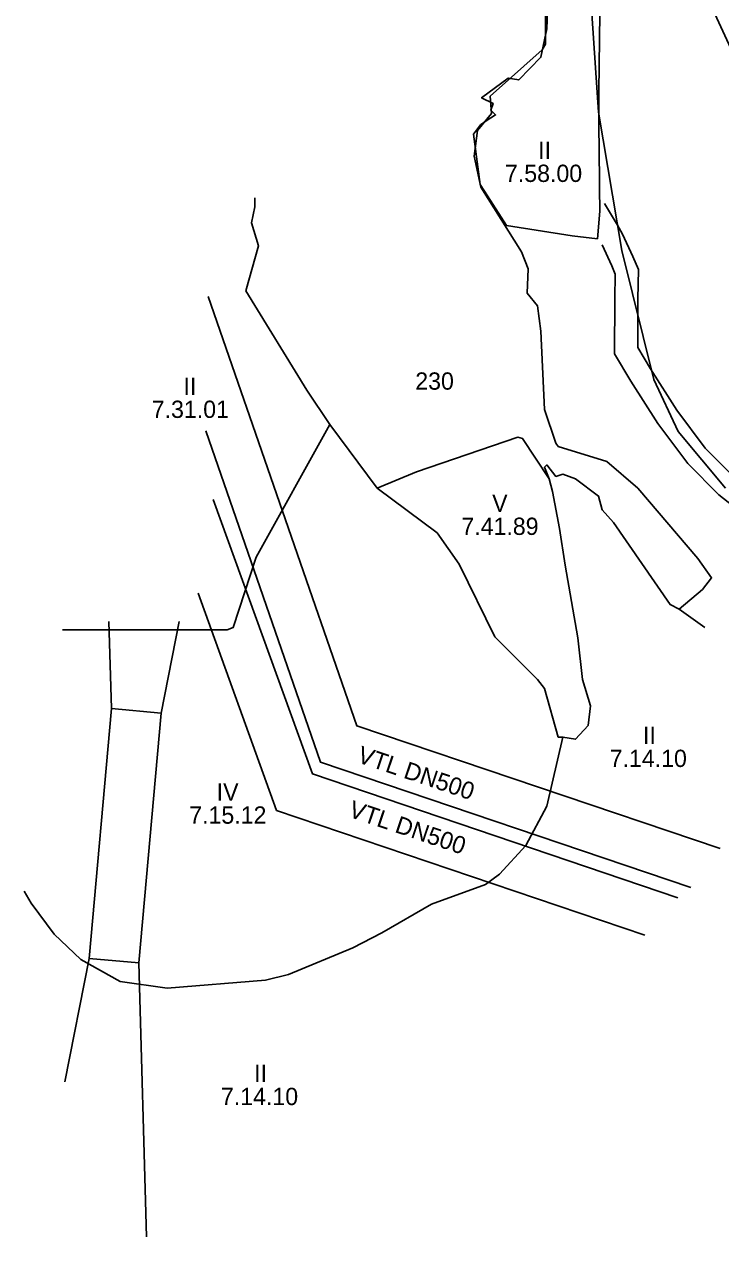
# Model space of a CAD drawing. Extents: x -694504 to -690518, y -983661 to -978958.
# Drawn here: x -693422 to -692818, y -983661 to -982609 of the extents above; entities that cross this region are included whole.
import ezdxf

# ---------------------------------------------------------------- set-up
doc = ezdxf.new("R2010")
doc.units = 0
for name, color, linetype in [('bezpečnostní pásmo', 7, 'Continuous'), ('BPEJ', 7, 'Continuous'), ('lokální biocentra', 7, 'Continuous'), ('lokální biokoridory', 7, 'Continuous'), ('plocha pro SLZ', 7, 'Continuous'), ('třídy přednosti v ochraně ZP', 7, 'Continuous'), ('VTL plynovod', 7, 'Continuous')]:
    doc.layers.add(name, color=color, linetype=linetype)

msp = doc.modelspace()

# ---------------------------------------------------------------- linework, layer by layer
at = {"layer": 'bezpečnostní pásmo'}
for points in [[(-692819.1, -983324.6), (-693134.2, -983218), (-693262.9, -982845.7)], [(-693271.8, -983102.9), (-693203.6, -983291.5), (-692884.2, -983399.8)]]:
    msp.add_lwpolyline(points, dxfattribs=at)
at = {"layer": 'BPEJ'}
for p, q in [((-693222.4, -982767.8), (-693222.4, -982760.1)), ((-692854.4, -983116.8), (-692832.2, -983132.9)), ((-693416.4, -983371.8), (-693422.5, -983361.5))]:
    msp.add_line(p, q, dxfattribs=at)
for points in [[(-692814.4, -983011.8), (-692855.4, -982962.8), (-692876.4, -982917.8), (-692904.4, -982805.8), (-692924.4, -982685.8), (-692931.4, -982582.8), (-692926.4, -982434.8), (-692926.4, -982406.8), (-692928.4, -982259.8), (-692918.4, -982237.8), (-692888.4, -982198.8), (-692863.4, -982207.8), (-692863.4, -982207.8), (-692864.4, -982295.8), (-692861.4, -982330.8), (-692862.4, -982461.8), (-692825.4, -982596.8), (-692794.4, -982663.8)], [(-692794.4, -982663.8), (-692825.4, -982596.8), (-692862.4, -982461.8), (-692861.4, -982330.8), (-692864.4, -982295.8), (-692863.4, -982207.8), (-692844.4, -982207.8), (-692817.4, -982201.8)], [(-692854.4, -983116.8), (-692834.4, -983099.8), (-692826.4, -983089.8), (-692838.4, -983072.8), (-692890.4, -983011.8), (-692917.4, -982988.8), (-692959.4, -982975.8), (-692961.4, -982972.8), (-692971.4, -982943.8), (-692974.4, -982875.8), (-692977.4, -982853.8), (-692986.4, -982842.8), (-692985.4, -982821.8), (-692991.4, -982806.8), (-693026.4, -982750.8), (-693032.4, -982723.8), (-693029.4, -982701.8), (-693017.4, -982686.8), (-693018.4, -982671.8), (-692973.4, -982631.8), (-692970.4, -982626.8), (-692970.4, -982559.8)], [(-693157.4, -982956.8), (-693177.4, -982926.8), (-693230.4, -982840.8), (-693219.4, -982801.8), (-693225.4, -982781.8), (-693222.4, -982767.8)], [(-693116.4, -983011.8), (-693157.4, -982956.8), (-693221.4, -983071.8), (-693241.4, -983132.8), (-693246.4, -983134.8), (-693389.4, -983134.8)], [(-692967.4, -983003.8), (-692971.4, -982993.8), (-692969.4, -982991.8), (-692961.4, -983001.8), (-692955.4, -982999.8), (-692944.4, -983003.8), (-692924.4, -983018.8), (-692921.4, -983030.8), (-692911.4, -983041.8), (-692862.4, -983112.8), (-692854.4, -983116.8)], [(-692955.4, -983227.8), (-692969.4, -983287.8), (-692987.4, -983321.8), (-693010.4, -983346.8), (-693022.4, -983355.8), (-693069.4, -983372.8), (-693112.4, -983397.8), (-693137.4, -983410.8), (-693193.4, -983433.8), (-693213.4, -983438.8), (-693298.4, -983445.8), (-693339.4, -983439.8), (-693373.4, -983420.8), (-693396.4, -983398.8), (-693416.4, -983371.8)]]:
    msp.add_lwpolyline(points, dxfattribs=at)
msp.add_lwpolyline([(-692967.4, -983003.8), (-692964.4, -983014.8), (-692958.4, -983046.8), (-692953.4, -983078.8), (-692942.4, -983141.8), (-692938.4, -983177.8), (-692931.4, -983200.8), (-692933.4, -983217.8), (-692944.4, -983229.8), (-692955.4, -983227.8), (-692959.4, -983227.8), (-692971.4, -983185.8), (-692977.4, -983177.8), (-693014.4, -983140.8), (-693045.4, -983077.8), (-693064.4, -983050.8), (-693116.4, -983011.8), (-693082.4, -982997.8), (-692994.4, -982967.8), (-692990.4, -982968.8), (-692967.4, -983003.8)], close=True, dxfattribs=at)
at = {"layer": 'lokální biocentra'}
msp.add_lwpolyline([(-692967.4, -982557.2), (-692969.2, -982613.5), (-692974.4, -982638.1), (-692993.6, -982657.8), (-693002.7, -982656.2), (-693025.9, -982673.3), (-693015.9, -982678.2), (-693017.9, -982684), (-693013.8, -982688.2), (-693022, -982693.4), (-693026.9, -982696.8), (-693032.8, -982704.8), (-693028.5, -982737.6), (-693027, -982748.5), (-693020.8, -982758.3), (-693004.4, -982784.1), (-692947.4, -982793.1), (-692925.4, -982795.5), (-692923.4, -982771.6), (-692923.7, -982751.7), (-692923.7, -982745.1), (-692924.2, -982695.9), (-692924.1, -982667.8), (-692923.2, -982599.9)], dxfattribs=at)
at = {"layer": 'lokální biokoridory'}
for points in [[(-692656.6, -983087.7), (-692694.3, -983066.4), (-692712.1, -983059), (-692716.8, -983055.4), (-692782.5, -983022), (-692806.6, -983002.7), (-692831.9, -982977.3), (-692856.5, -982944.3), (-692879.5, -982908.5), (-692890.5, -982890), (-692890.3, -982847.9), (-692889.9, -982822.3), (-692894.6, -982811), (-692903.6, -982791.5), (-692908, -982783.9), (-692919.3, -982764.9)], [(-692921.4, -982800.7), (-692912.9, -982819.1), (-692909.9, -982826.2), (-692910.3, -982847.7), (-692910.6, -982895.5), (-692896.5, -982919), (-692872.9, -982955.7), (-692847, -982990.4), (-692820, -983017.6), (-692793.3, -983038.9), (-692727.5, -983072.4), (-692722.2, -983076.5), (-692703.1, -983084.4), (-692665.5, -983105.6)]]:
    msp.add_lwpolyline(points, dxfattribs=at)
at = {"layer": 'plocha pro SLZ'}
for p, q in [((-693346.9, -983203.2), (-693349.1, -983127.6)), ((-693303.8, -983207), (-693288.2, -983127.6)), ((-693387.2, -983527), (-693366.1, -983420)), ((-693316.4, -983661.3), (-693323, -983423.8))]:
    msp.add_line(p, q, dxfattribs=at)
msp.add_lwpolyline([(-693346.9, -983203.2), (-693366.1, -983420), (-693323, -983423.8), (-693303.8, -983207)], close=True, dxfattribs=at)
at = {"layer": 'VTL plynovod'}
for points in [[(-693265, -982962.1), (-693165.6, -983249.6), (-692844.4, -983358.2)], [(-693258.6, -983021.9), (-693172.5, -983259.8), (-692855.7, -983367.2)]]:
    msp.add_lwpolyline(points, dxfattribs=at)

# ---------------------------------------------------------------- texts
at = {"layer": 'třídy přednosti v ochraně ZP'}
for s, p in [('II', (-692976.8, -982726.3)), ('7.58.00', (-693005.6, -982746.3)), ('230', (-693083.4, -982926.5)), ('II', (-693284.4, -982931)), ('7.31.01', (-693311.9, -982951)), ('V', (-693016.7, -983032.5)), ('7.41.89', (-693043.4, -983052.5)), ('II', (-692885.9, -983233.8)), ('7.14.10', (-692914.8, -983253.8)), ('IV', (-693255.6, -983283)), ('7.15.12', (-693279.4, -983303)), ('II', (-693223.1, -983527.1)), ('7.14.10', (-693251.9, -983547.1))]:
    msp.add_text(s, height=15, dxfattribs=at).set_placement(p)
at = {"layer": 'VTL plynovod'}
for p in [(-693134.6, -983249.5), (-693142.1, -983296.7)]:
    msp.add_text('VTL DN500', height=15, rotation=341.5, dxfattribs=at).set_placement(p)

doc.saveas('drawing.dxf')
